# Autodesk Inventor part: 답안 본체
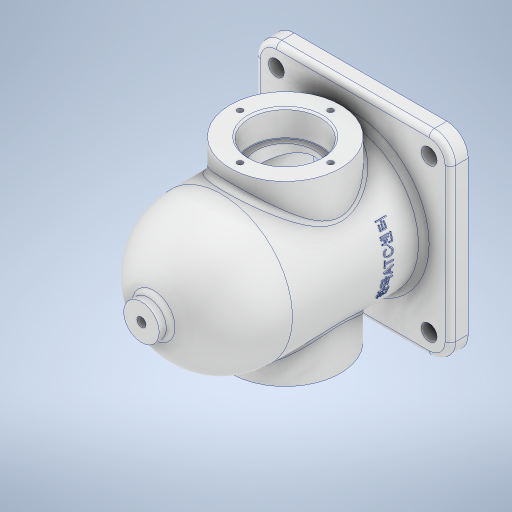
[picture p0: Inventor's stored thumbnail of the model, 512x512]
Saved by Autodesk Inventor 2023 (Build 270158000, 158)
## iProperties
Created: 2025-04
Part Number: 답안 본체
Material: 알루미늄 6061
Document SubType Name: Modeling
Designer: ADMIN_PC
Density: 2.7 g/cm^3
Appearance: 알루미늄 - 평지
Mass: 865.906 g
Surface Area: 800.755 cm^2
Volume: 320.706 cm^3
Author: ADMIN_PC
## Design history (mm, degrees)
sketch "스케치1"
  geometry: C1 r 40 at (0, 0); 1 further point
  constraints: 1 centre point, 1 coincident
  dimensions: "d0" = 80 diameter of C1
extrude "돌출1" new body sketch "스케치1" stored distance "d1" = 84; taper "d2" = 0 deg
sketch "스케치2"
  geometry: L1 (55, 55)-(-55, 55); L2 (-55, 55)-(-55, -55); L3 (-55, -55)-(55, -55); L4 (55, -55)-(55, 55); L5 (55, 55)-(-55, -55); L6 (-55, 55)-(55, -55); 1 further point
  constraints: 12 end point, 2 midpoint, 2 parallel, 1 horizontal, 1 perpendicular
  dimensions: "d3" = 110 distance of L3.end L2.end; "d4" = 110 distance of L2.end L1.end
extrude "돌출2" join sketch "스케치2" distance "d5" = 10; taper "d6" = 0 deg
sketch "스케치4"
  geometry: C1 r 10 at (0, 0); 1 further point
  constraints: 1 centre point, 1 coincident
  dimensions: "d9" = 20 diameter of C1
extrude "돌출3" join sketch "스케치4" distance "d10" = 45; taper "d11" = 0 deg
sketch "스케치3"
  geometry: L1 (77, 0)-(-77, 0) reference; L2 (0, -58.8)-(0, 58.8) reference; L3 (40, 42)-(-40, 42) reference; L4 (40, 42)-(0, 42); L5 (0, 42)-(0, 82); A1 r 40 centre (0, 42) between (40, 42) and (0, 82); 1 further point
  constraints: 4 end point, 2 point on circle, 1 centre point, 1 collinear, 1 midpoint, 1 perpendicular, 1 point on line
  dimensions: "d8" = 40 radius of A1
revolve "회전1" sketch "스케치3" stored, may be unused: angle "d12" = 90 deg
sketch "스케치8"
  geometry: L1 (-55, -42)-(55, -42) reference; L2 (0, -67.8)-(0, 112.8) reference; C1 r 31 at (0, 6)
  constraints: 1 centre point, 1 point on line
  dimensions: "d14" = 62 diameter of C1; "d17" = 48 distance from line of L1 C1.centre
extrude "돌출4" join sketch "스케치8" stored distance "d15" = 100; taper "d16" = 0 deg
sketch "스케치9"
  geometry: L1 (76.691, 6)-(-85.662, 6); L2 (55, -42)-(-55, -42) reference; L3 (0, -67.8)-(0, 112.8) reference; L4 (50, -25)-(50, 37) reference; L5 (50, 6)-(35, 6); L6 (35, 6)-(35, 26); L7 (35, 26)-(50, 26); L8 (50, 26)-(50, 6); L9 (35, 6)-(-35, 6); L10 (-35, 6)-(-35, 22.5); L11 (-35, 22.5)-(35, 22.5); L12 (35, 22.5)-(35, 6); L13 (-50, 37)-(-50, -25) reference; L14 (-35, 6)-(-50, 6); L15 (-50, 6)-(-50, 26); L16 (-50, 26)-(-35, 26); L17 (-35, 26)-(-35, 6); 3 further points
  constraints: 26 end point, 6 parallel, 4 horizontal, 3 perpendicular, 2 point on line, 2 symmetric about line, 1 midpoint
  dimensions: "d19" = 48 distance between parallel lines of L2 L1; "d20" = 15 distance of L6.end L7.end; "d21" = 40 diameter of L7 L1; "d22" = 33 diameter of L11 L1
revolve "회전2" sketch "스케치9" stored, may be unused: angle "d23" = 90 deg
sketch "스케치10"
  geometry: C1 r 32 at (0, 0); 1 further point
  constraints: 1 centre point, 1 coincident
  dimensions: "d24" = 64 diameter of C1
extrude "돌출5" cut sketch "스케치10" distance "d25" = 84; taper "d26" = 0 deg
sketch "스케치11"
  geometry: L1 (32, 42)-(-32, 42) reference; L2 (-32, 42)-(0, 42); L3 (0, 74)-(0, 42); L4 (0, -67.8)-(0, 112.8) reference; A1 r 32 centre (0, 42) between (0, 74) and (-32, 42); 1 further point
  constraints: 4 end point, 2 point on circle, 1 centre point, 1 horizontal, 1 midpoint, 1 perpendicular
  dimensions: "d27" = 32 radius of A1
revolve "회전3" sketch "스케치11" stored, may be unused: angle "d28" = 90 deg
sketch "스케치12"
  geometry: C1 r 10 at (0, 0) reference; 2 further points
  constraints: 1 coincident
hole "구멍1" sketch "스케치12" at (0, 0) diameter "d29" = 5.1881; stored, may be unused: countersink angle "d33" = 90 deg, drill point angle "d35" = 0 deg; dims "d30" = 30, "d31" = 12, "d32" = 5, "d34" = 16
sketch "스케치13"
  geometry: L1 (0, 73.8)-(0, -106.8) reference; C1 r 20 at (0, 0) reference; 2 further points
  constraints: 1 point on line
  dimensions: "d36" = 25.5 distance of point (0, -25.5) C1.centre
hole "구멍2" sketch "스케치13" at (0, -25.5) diameter "d37" = 3.242; stored, may be unused: countersink angle "d41" = 90 deg, drill point angle "d43" = 118 deg; dims "d38" = 8, "d39" = 4, "d40" = 2, "d42" = 10
sketch "스케치14"
  geometry: L1 (55, 55)-(-55, 55) reference; L2 (-55, 55)-(-55, -55) reference; 2 further points
  dimensions: "d47" = 12 distance from line of L1 point (-43, 43); "d48" = 12 distance from line of L2 point (-43, 43)
hole "구멍3" sketch "스케치14" at (-43, 43) diameter "d49" = 9; stored, may be unused: countersink angle "d53" = 90 deg, drill point angle "d55" = 118 deg; dims "d50" = 8, "d51" = 4, "d52" = 2, "d54" = 10
chamfer "모따기1" distance "d62" = 1; stored, may be unused: second distance "d63" = 2, angle "d64" = 45 deg
fillet "모깎기1" dims "d65" = 0.3
fillet "모깎기2" dims "d66" = 12
fillet "모깎기3" dims "d67" = 3
node "작업 평면1"
sketch "스케치15"
  geometry: L1 (0, -67.8)-(0, 112.8) reference; L2 (43, -42)-(-43, -42) reference; 2 further points
  constraints: 1 point on line, 1 other
  dimensions: "d69" = 30 distance from line of L2 point (0, -12)
feature "엠보싱1" sketch "스케치15" dims "d70" = 0.5, "d71" = 0
feature "̩耀̫耀̭耀̯耀̱耀̳耀̵耀̷耀" dims "d0" = 80, "d1" = 84, "d2" = 0, "d3" = 110, "d4" = 110, "d5" = 10, "d6" = 0, "d8" = 40, "d9" = 20, "d10" = 45, "d11" = 0, "d12" = 90 deg, "d14" = 62, "d15" = 100, "d16" = 0, "d17" = 48, "d19" = 48, "d20" = 15, "d21" = 40, "d22" = 33, "d23" = 90 deg, "d24" = 64, "d25" = 84, "d26" = 0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
node "솔리드1"
pattern_circular "원형 패턴1" dims angle "d45" = 360 deg
mirror "미러1"
pattern_linear "직사각형 패턴1" dims "d58" = 86, "d61" = 86
feature "A9D066F2-1C7D-4E18-AEED-F7BC21143FA4" dims "d49" = 9, "d50" = 8, "d51" = 4, "d52" = 2, "d53" = 90 deg, "d54" = 10, "d55" = 118 deg
